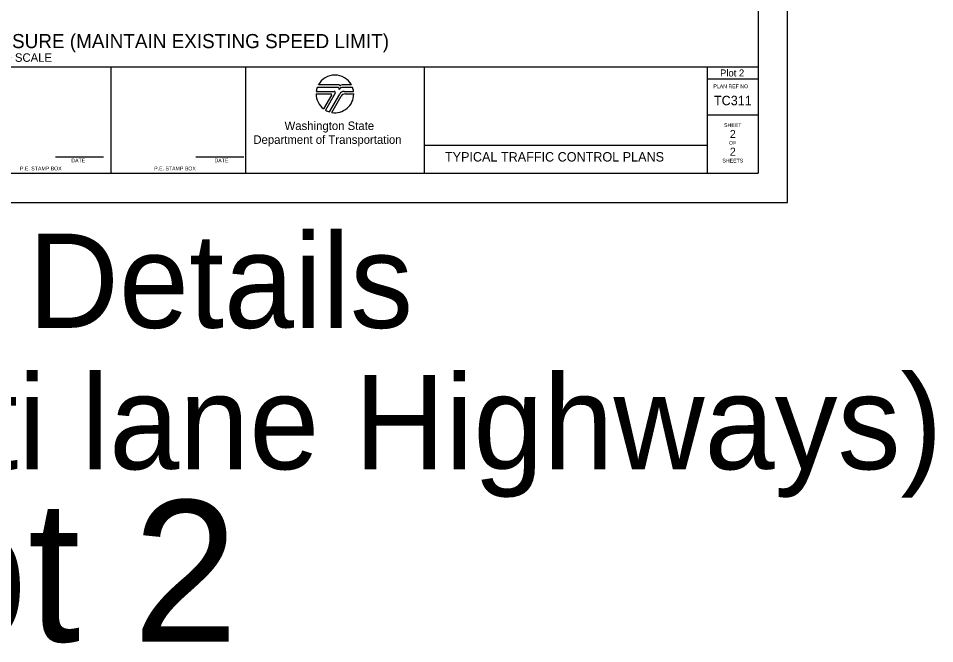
# Model space of a CAD drawing. Extents: x 99999.1 to 100055.7, y 99995 to 100013.2.
# Drawn here: x 100027.9 to 100037.62, y 99995.01 to 100001.64 of the extents above; entities that cross this region are included whole.
import ezdxf

# ---------------------------------------------------------------- set-up
doc = ezdxf.new("R2010")
doc.units = 0
for name, color, linetype in [('SH_DE_DetailHeading1Text', 7, 'Continuous'), ('SH_GI_PlotLimits', 7, 'Continuous'), ('SH_GI_SheetBorder', 7, 'Continuous'), ('SH_GI_SheetLocationText', 7, 'Continuous'), ('SH_GI_SheetTextInCells', 7, 'Continuous'), ('SH_GI_TitleBlockText', 7, 'Continuous'), ('SH_GI_WSDOTLogo', 7, 'Continuous')]:
    doc.layers.add(name, color=color, linetype=linetype)

msp = doc.modelspace()

# ---------------------------------------------------------------- linework, layer by layer
at = {"layer": 'SH_GI_PlotLimits'}
msp.add_lwpolyline([(100019.0625, 99999.6875), (100036.0625, 99999.6875), (100036.0625, 100010.6875), (100019.0625, 100010.6875)], close=True, dxfattribs=at)
at = {"layer": 'SH_GI_SheetBorder'}
for p, q in [((100035.75, 100010.375), (100035.75, 100000)), ((100020, 100001.1259), (100035.75, 100001.1259)), ((100028.8828, 100000), (100028.8828, 100001.1259)), ((100030.3089, 100001.1259), (100030.3089, 100000)), ((100032.2055, 100001.1259), (100032.2055, 100000)), ((100035.2079, 100001.1259), (100035.2079, 100000)), ((100035.2079, 100001.0008), (100035.75, 100001.0008)), ((100035.2079, 100000.6176), (100035.75, 100000.6176)), ((100032.2055, 100000.2955), (100035.2079, 100000.2955)), ((100028.2903, 100000.1733), (100028.802, 100000.1733)), ((100029.7797, 100000.1733), (100030.2914, 100000.1733)), ((100020, 100000), (100035.75, 100000))]:
    msp.add_line(p, q, dxfattribs=at)
at = {"layer": 'SH_GI_WSDOTLogo'}
for p, q in [((100031.059, 100000.8661), (100031.2496, 100000.8661)), ((100031.2894, 100000.9094), (100031.0697, 100000.9094)), ((100031.303, 100000.9354), (100031.0815, 100000.9354)), ((100031.433, 100000.9354), (100031.3351, 100000.9354)), ((100031.343, 100000.9094), (100031.3429, 100000.9094)), ((100031.4448, 100000.9094), (100031.343, 100000.9094)), ((100031.3558, 100000.8661), (100031.4555, 100000.8661)), ((100031.0572, 100000.84), (100031.2148, 100000.84)), ((100031.222, 100000.8277), (100031.1364, 100000.6807)), ((100031.261, 100000.8464), (100031.1567, 100000.6672)), ((100031.1989, 100000.6487), (100031.3089, 100000.839)), ((100031.2244, 100000.6428), (100031.3242, 100000.8156)), ((100031.3655, 100000.8394), (100031.4572, 100000.8394))]:
    msp.add_line(p, q, dxfattribs=at)
for centre, radius, start, end in [((100031.2572, 100000.84), 0.2, 28.47865, 151.53204), ((100031.2572, 100000.84), 0.2, 159.69598, 172.50569), ((100031.2497, 100000.853), 0.0131, 329.76834, 90), ((100031.2894, 100000.8946), 0.0148, 327.8418, 89.99855), ((100031.3429, 100000.861), 0.0484, 89.99529, 147.82376), ((100031.303, 100000.9263), 0.00903, 329.87418, 90.00328), ((100031.3558, 100000.8119), 0.0542, 90, 149.99738), ((100031.3352, 100000.9066), 0.0287, 90.00721, 148.16763), ((100031.2572, 100000.84), 0.2, 7.49431, 20.29406), ((100031.2572, 100000.84), 0.2, 179.99864, 232.84327), ((100031.2149, 100000.8318), 0.0082, 329.74356, 90), ((100031.2572, 100000.84), 0.2, 260.54554, 359.80857), ((100031.3654, 100000.7918), 0.0476, 90, 150.05432), ((100031.2572, 100000.84), 0.2, 239.79292, 253.0448)]:
    msp.add_arc(centre, radius, start, end, dxfattribs=at)

# ---------------------------------------------------------------- texts
at = {"layer": 'SH_DE_DetailHeading1Text'}
for s, height, p in [('FREEWAY (2+ LANES): RIGHT SHOULDER CLOSURE (MAINTAIN EXISTING SPEED LIMIT)', 0.15, (100023.3333, 100001.3259)), ('NOT TO SCALE', 0.09, (100027.3727, 100001.1809))]:
    msp.add_text(s, height=height, rotation=360, dxfattribs=at).set_placement(p)
at = {"layer": 'SH_GI_SheetBorder'}
msp.add_text('PLAN REF NO', height=0.040032, dxfattribs=at).set_placement((100035.2747, 100000.9008))
at = {"layer": 'SH_GI_SheetLocationText'}
for s, height, p in [('Plot 2', 0.075, (100035.3454, 100001.025)), ('Ramp Details', 1, (100024.0609, 99998.3571)), ('(45+ mph Multi lane Highways)', 1, (100019.3114, 99996.8571)), ('Plot 2', 1.5, (100025.0998, 99995.0267))]:
    msp.add_text(s, height=height, dxfattribs=at).set_placement(p)
at = {"layer": 'SH_GI_SheetTextInCells'}
for s, height, p in [('Washington State', 0.090072, (100030.7229, 100000.4571)), ('SHEET', 0.04003, (100035.3877, 100000.4896)), ('Department of Transportation', 0.090072, (100030.3916, 100000.3101)), ('OF', 0.04003, (100035.4406, 100000.3008)), ('DATE', 0.04003, (100028.4597, 100000.1141)), ('DATE', 0.04003, (100029.9794, 100000.1141)), ('SHEETS', 0.04003, (100035.3698, 100000.112)), ('P.E. STAMP BOX', 0.040032, (100027.915, 100000.0286)), ('P.E. STAMP BOX', 0.040032, (100029.339, 100000.0286))]:
    msp.add_text(s, height=height, dxfattribs=at).set_placement(p)
at = {"layer": 'SH_GI_TitleBlockText'}
for s, height, p in [('TC311', 0.1, (100035.2803, 100000.72)), ('2', 0.085, (100035.4493, 100000.3723)), ('2', 0.085, (100035.4493, 100000.1843)), ('TYPICAL TRAFFIC CONTROL PLANS', 0.1, (100032.4251, 100000.1224))]:
    msp.add_text(s, height=height, dxfattribs=at).set_placement(p)

doc.saveas('drawing.dxf')
